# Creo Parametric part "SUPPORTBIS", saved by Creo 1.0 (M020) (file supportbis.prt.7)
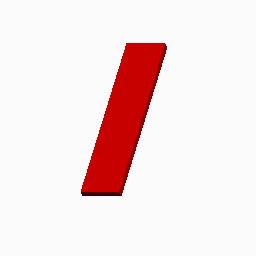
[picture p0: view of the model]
Units: millimeter Newton Second (mmNs); MM, TONNE, SECS
Materials in the file: FE20

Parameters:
  PTC_MATERIAL_NAME = "FE20"

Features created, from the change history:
  datum axis "A_1"
  datum plane "DTM1"
  datum plane "DTM2"
  datum axis "A_2"
  datum plane "DTM3"
  datum plane "DTM4"
  datum point "PNT0"

Other named items: SUPPORTBIS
